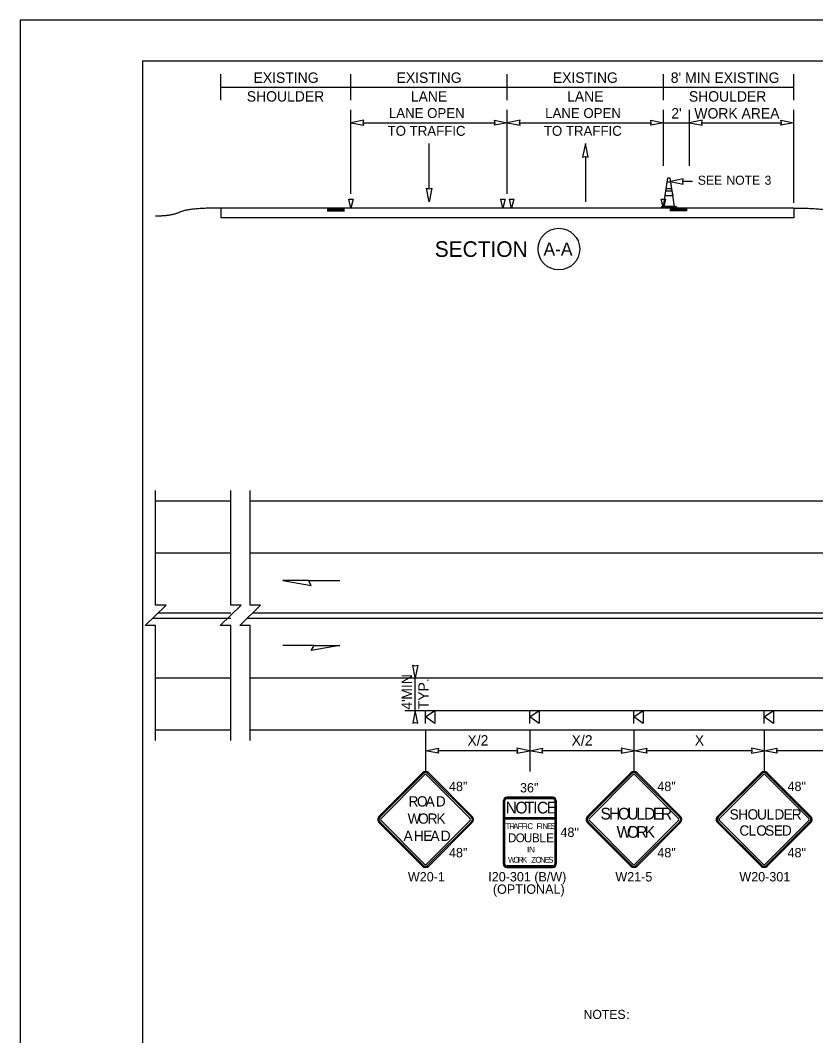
# Model space of a CAD drawing. Extents: x 99999.1 to 100055.7, y 99995 to 100013.2.
# Drawn here: x 99999.06 to 100005.17, y 100002.89 to 100010.69 of the extents above; entities that cross this region are included whole.
import ezdxf

# ---------------------------------------------------------------- set-up
doc = ezdxf.new("R2010")
doc.units = 0
for name, color, linetype in [('RD_ED_ShoulderPavedEdge', 7, 'Continuous'), ('RD_MK_LineDblYellowCenter', 7, 'Continuous'), ('RD_MK_LineEdgeWhite', 7, 'Continuous'), ('SH_GI_GeneralNotesBodyText', 7, 'Continuous'), ('SH_GI_PlotLimits', 7, 'Continuous'), ('SH_GI_SheetBorder', 7, 'Continuous'), ('SH_TI_WZSectionCut', 7, 'Continuous'), ('TR_SN_ConstructionSigns', 7, 'Continuous'), ('TR_WZ_ArrowLeftStrRightTurn', 7, 'Continuous'), ('TR_WZ_PortableSignMountBlk-Org', 7, 'Continuous'), ('TR_WZ_PortableSignMountBlk-Wht', 7, 'Continuous'), ('TR_WZ_TrafficConeElev', 7, 'Continuous'), ('TR_WZ_WorkZoneDetails', 7, 'Continuous'), ('TR_WZ_WorkZoneTextCurrent', 7, 'Continuous')]:
    doc.layers.add(name, color=color, linetype=linetype)

msp = doc.modelspace()

# ---------------------------------------------------------------- linework, layer by layer
at = {"layer": 'RD_ED_ShoulderPavedEdge'}
for p, q in [((100000.1016, 100006.9957), (100000.6783, 100006.9957)), ((100000.8283, 100006.9957), (100015.62, 100006.9957)), ((100000.1016, 100005.2357), (100000.6783, 100005.2357)), ((100000.8283, 100005.2357), (100015.62, 100005.2357))]:
    msp.add_line(p, q, dxfattribs=at)
at = {"layer": 'RD_MK_LineDblYellowCenter'}
for p, q in [((100000.081, 100006.0957), (100000.6783, 100006.0957)), ((100000.1223, 100006.1357), (100000.6783, 100006.1357)), ((100000.8076, 100006.0957), (100015.62, 100006.0957)), ((100000.849, 100006.1357), (100015.62, 100006.1357))]:
    msp.add_line(p, q, dxfattribs=at)
at = {"layer": 'RD_MK_LineEdgeWhite'}
for p, q in [((100000.1016, 100006.5957), (100000.6783, 100006.5957)), ((100000.8283, 100006.5957), (100015.62, 100006.5957)), ((100000.1016, 100005.6357), (100000.6783, 100005.6357)), ((100000.8283, 100005.6357), (100015.62, 100005.6357))]:
    msp.add_line(p, q, dxfattribs=at)
at = {"layer": 'SH_GI_PlotLimits'}
msp.add_lwpolyline([(99999.0625, 99999.6875), (100016.0625, 99999.6875), (100016.0625, 100010.6875), (99999.0625, 100010.6875)], close=True, dxfattribs=at)
at = {"layer": 'SH_GI_SheetBorder'}
for q in [(100000, 100000), (100015.75, 100010.375)]:
    msp.add_line((100000, 100010.375), q, dxfattribs=at)
at = {"layer": 'SH_TI_WZSectionCut'}
for p, q in [((100000.6021, 100010.075), (100000.6021, 100010.275)), ((100001.6021, 100010.075), (100001.6021, 100010.275)), ((100002.8021, 100010.075), (100002.8021, 100010.275)), ((100004.0021, 100010.075), (100004.0021, 100010.275)), ((100005.0021, 100010.075), (100005.0021, 100010.275)), ((100000.6021, 100010.175), (100001.6021, 100010.175)), ((100001.6021, 100010.175), (100002.8021, 100010.175)), ((100002.8021, 100010.175), (100004.0021, 100010.175)), ((100004.0021, 100010.175), (100005.0021, 100010.175)), ((100001.6021, 100009.3547), (100001.6021, 100010.001)), ((100002.8021, 100009.3547), (100002.8021, 100010.001)), ((100004.0021, 100009.57), (100004.0021, 100010.001)), ((100004.2021, 100009.57), (100004.2021, 100010.001)), ((100005.0021, 100009.2849), (100005.0021, 100010.001)), ((100001.6958, 100009.901), (100002.7084, 100009.901)), ((100002.8958, 100009.901), (100003.9084, 100009.901)), ((100004.0021, 100009.901), (100004.2021, 100009.901)), ((100004.2958, 100009.901), (100004.9084, 100009.901)), ((100000.6021, 100009.2449), (100000.6021, 100009.1699)), ((100005.0021, 100009.2449), (100000.6021, 100009.2449)), ((100001.4191, 100009.2397), (100001.5521, 100009.2397)), ((100001.4191, 100009.2341), (100001.5521, 100009.2341)), ((100001.4191, 100009.2284), (100001.5521, 100009.2284)), ((100001.4191, 100009.2232), (100001.5521, 100009.2232)), ((100004.1851, 100009.2393), (100004.0521, 100009.2393)), ((100004.1851, 100009.2337), (100004.0521, 100009.2337)), ((100004.1851, 100009.228), (100004.0521, 100009.228)), ((100004.1851, 100009.2228), (100004.0521, 100009.2228)), ((100005.0021, 100009.2449), (100005.0021, 100009.1699)), ((100005.0021, 100009.1699), (100000.6021, 100009.1699))]:
    msp.add_line(p, q, dxfattribs=at)
for points in [[(100001.6021, 100009.901), (100001.7004, 100009.8817), (100001.6958, 100009.901), (100001.7004, 100009.9203)], [(100002.8021, 100009.901), (100002.7038, 100009.8817), (100002.7084, 100009.901), (100002.7038, 100009.9203)], [(100002.8021, 100009.901), (100002.9004, 100009.8817), (100002.8958, 100009.901), (100002.9004, 100009.9203)], [(100004.0021, 100009.901), (100003.9038, 100009.8817), (100003.9084, 100009.901), (100003.9038, 100009.9203)], [(100004.2021, 100009.901), (100004.3004, 100009.8817), (100004.2958, 100009.901), (100004.3004, 100009.9203)], [(100005.0021, 100009.901), (100004.9038, 100009.8817), (100004.9084, 100009.901), (100004.9038, 100009.9203)], [(100001.5854, 100009.3147), (100001.6188, 100009.3147), (100001.6021, 100009.2449)], [(100002.7521, 100009.3147), (100002.7854, 100009.3147), (100002.7688, 100009.2449)], [(100002.8188, 100009.3147), (100002.8521, 100009.3147), (100002.8355, 100009.2449)], [(100003.9854, 100009.3147), (100004.0188, 100009.3147), (100004.0021, 100009.2449)]]:
    msp.add_lwpolyline(points, close=True, dxfattribs=at)
msp.add_circle((100003.1987, 100008.93), 0.16, dxfattribs=at)
for points in [[(100000.6021, 100009.2449), (100000.3509, 100009.2449), (100000.2255, 100009.1828), (100000.1, 100009.1828)], [(100005.0021, 100009.2449), (100005.2533, 100009.2451), (100005.3788, 100009.183), (100005.5043, 100009.1831)]]:
    msp.add_open_spline(points, degree=2, dxfattribs=at)
at = {"layer": 'TR_SN_ConstructionSigns'}
for p, q in [((100002.1514, 100004.9058), (100001.8173, 100004.5717)), ((100002.1574, 100004.8999), (100001.8233, 100004.5658)), ((100002.5273, 100004.5658), (100002.1932, 100004.8999)), ((100002.5333, 100004.5717), (100002.1991, 100004.9058)), ((100003.7514, 100004.9058), (100003.4173, 100004.5717)), ((100003.7574, 100004.8999), (100003.4233, 100004.5658)), ((100004.1273, 100004.5658), (100003.7932, 100004.8999)), ((100004.1333, 100004.5717), (100003.7991, 100004.9058)), ((100004.7514, 100004.9058), (100004.4173, 100004.5717)), ((100004.7574, 100004.8999), (100004.4233, 100004.5658)), ((100005.1273, 100004.5658), (100004.7932, 100004.8999)), ((100005.1333, 100004.5717), (100004.7991, 100004.9058)), ((100001.8332, 100004.5558), (100002.1673, 100004.8899)), ((100002.1832, 100004.8899), (100002.5173, 100004.5558)), ((100003.4332, 100004.5558), (100003.7673, 100004.8899)), ((100003.7832, 100004.8899), (100004.1173, 100004.5558)), ((100004.4332, 100004.5558), (100004.7673, 100004.8899)), ((100004.7832, 100004.8899), (100005.1173, 100004.5558)), ((100002.7728, 100004.2053), (100002.7728, 100004.6947)), ((100002.7728, 100004.6947), (100002.7728, 100004.2053)), ((100002.7728, 100004.6947), (100002.7728, 100004.2053)), ((100002.777, 100004.6947), (100002.777, 100004.2053)), ((100002.784, 100004.5604), (100002.784, 100004.6947)), ((100002.7981, 100004.72), (100003.1525, 100004.72)), ((100003.1525, 100004.72), (100002.7981, 100004.72)), ((100003.1525, 100004.72), (100002.7981, 100004.72)), ((100003.1525, 100004.7158), (100002.7981, 100004.7158)), ((100002.7981, 100004.7088), (100003.1525, 100004.7088)), ((100003.1665, 100004.6947), (100003.1665, 100004.5604)), ((100003.1736, 100004.2053), (100003.1736, 100004.6947)), ((100003.1778, 100004.6947), (100003.1778, 100004.2053)), ((100003.1778, 100004.2053), (100003.1778, 100004.6947)), ((100003.1778, 100004.2053), (100003.1778, 100004.6947)), ((100001.8173, 100004.524), (100002.1514, 100004.1899)), ((100001.8233, 100004.53), (100002.1574, 100004.1959)), ((100002.1673, 100004.2058), (100001.8332, 100004.5399)), ((100002.5173, 100004.5399), (100002.1832, 100004.2058)), ((100002.1932, 100004.1959), (100002.5273, 100004.53)), ((100002.1991, 100004.1899), (100002.5333, 100004.524)), ((100002.784, 100004.5604), (100002.784, 100004.5604)), ((100003.1665, 100004.5604), (100002.784, 100004.5604)), ((100002.784, 100004.5604), (100002.784, 100004.5534)), ((100002.784, 100004.5534), (100002.784, 100004.5604)), ((100002.784, 100004.5534), (100003.1665, 100004.5534)), ((100002.784, 100004.2053), (100002.784, 100004.5534)), ((100003.1665, 100004.5534), (100003.1665, 100004.5604)), ((100003.1665, 100004.5604), (100003.1665, 100004.5534)), ((100003.1665, 100004.5534), (100003.1665, 100004.2053)), ((100003.4173, 100004.524), (100003.7514, 100004.1899)), ((100003.4233, 100004.53), (100003.7574, 100004.1959)), ((100003.7673, 100004.2058), (100003.4332, 100004.5399)), ((100004.1173, 100004.5399), (100003.7832, 100004.2058)), ((100003.7932, 100004.1959), (100004.1273, 100004.53)), ((100003.7991, 100004.1899), (100004.1333, 100004.524)), ((100004.4173, 100004.524), (100004.7514, 100004.1899)), ((100004.4233, 100004.53), (100004.7574, 100004.1959)), ((100004.7673, 100004.2058), (100004.4332, 100004.5399)), ((100005.1173, 100004.5399), (100004.7832, 100004.2058)), ((100004.7932, 100004.1959), (100005.1273, 100004.53)), ((100004.7991, 100004.1899), (100005.1333, 100004.524)), ((100003.1525, 100004.1913), (100002.7981, 100004.1913)), ((100002.7981, 100004.1842), (100003.1525, 100004.1842)), ((100003.1525, 100004.18), (100002.7981, 100004.18)), ((100002.7981, 100004.18), (100003.1525, 100004.18)), ((100002.7981, 100004.18), (100003.1525, 100004.18))]:
    msp.add_line(p, q, dxfattribs=at)
for centre, radius, start, end in [((100002.1753, 100004.882), 0.0338, 45, 135), ((100002.1753, 100004.882), 0.0253, 45, 135), ((100002.1753, 100004.882), 0.0113, 45, 135), ((100003.7753, 100004.882), 0.0338, 45, 135), ((100003.7753, 100004.882), 0.0253, 45, 135), ((100003.7753, 100004.882), 0.0113, 45, 135), ((100004.7753, 100004.882), 0.0338, 45, 135), ((100004.7753, 100004.882), 0.0253, 45, 135), ((100004.7753, 100004.882), 0.0113, 45, 135), ((100002.7981, 100004.6947), 0.0253, 90, 180), ((100002.7981, 100004.6947), 0.0253, 90, 180), ((100002.7981, 100004.6947), 0.0253, 90, 180), ((100002.7981, 100004.6947), 0.0211, 90, 180.00001), ((100002.7981, 100004.6947), 0.0141, 90, 180.00001), ((100003.1525, 100004.6947), 0.0253, 0, 90), ((100003.1525, 100004.6947), 0.0253, 0, 90), ((100003.1525, 100004.6947), 0.0253, 0, 90), ((100003.1525, 100004.6947), 0.0211, 0, 90), ((100003.1525, 100004.6947), 0.0141, 0, 90), ((100001.8412, 100004.5479), 0.0338, 135, 225.00001), ((100001.8412, 100004.5479), 0.0253, 135, 225.00001), ((100001.8412, 100004.5479), 0.0113, 135, 225.00001), ((100002.5094, 100004.5479), 0.0113, 315.00002, 45), ((100002.5094, 100004.5479), 0.0253, 315.00002, 45), ((100002.5094, 100004.5479), 0.0338, 315.00001, 45.00001), ((100003.4412, 100004.5479), 0.0338, 135, 225.00001), ((100003.4412, 100004.5479), 0.0253, 135, 225.00001), ((100003.4412, 100004.5479), 0.0113, 135, 225.00001), ((100004.1094, 100004.5479), 0.0113, 315.00002, 45), ((100004.1094, 100004.5479), 0.0253, 315.00002, 45), ((100004.1094, 100004.5479), 0.0338, 315.00001, 45.00001), ((100004.4412, 100004.5479), 0.0338, 135, 225.00001), ((100004.4412, 100004.5479), 0.0253, 135, 225.00001), ((100004.4412, 100004.5479), 0.0113, 135, 225.00001), ((100005.1094, 100004.5479), 0.0113, 315.00002, 45), ((100005.1094, 100004.5479), 0.0253, 315.00002, 45), ((100005.1094, 100004.5479), 0.0338, 315.00001, 45.00001), ((100002.1753, 100004.2138), 0.0253, 225.00001, 315.00002), ((100002.1753, 100004.2138), 0.0113, 225.00001, 315.00002), ((100002.7981, 100004.2053), 0.0253, 180, 270.00001), ((100002.7981, 100004.2053), 0.0253, 180, 270.00001), ((100002.7981, 100004.2053), 0.0253, 180, 270.00001), ((100002.7981, 100004.2053), 0.0211, 180.00001, 270), ((100002.7981, 100004.2053), 0.0141, 180.00001, 270), ((100003.1525, 100004.2053), 0.0253, 270.00001, 0.00001), ((100003.1525, 100004.2053), 0.0253, 270.00001, 0.00001), ((100003.1525, 100004.2053), 0.0211, 270, 0.00001), ((100003.1525, 100004.2053), 0.0141, 270, 0.00001), ((100003.1525, 100004.2053), 0.0253, 270.00001, 0.00001), ((100003.7753, 100004.2138), 0.0253, 225.00001, 315.00002), ((100003.7753, 100004.2138), 0.0113, 225.00001, 315.00002), ((100004.7753, 100004.2138), 0.0253, 225.00001, 315.00002), ((100004.7753, 100004.2138), 0.0113, 225.00001, 315.00002), ((100002.1753, 100004.2138), 0.0338, 225.00001, 315.00001), ((100003.7753, 100004.2138), 0.0338, 225.00001, 315.00001), ((100004.7753, 100004.2138), 0.0338, 225.00001, 315.00001)]:
    msp.add_arc(centre, radius, start, end, dxfattribs=at)
at = {"layer": 'TR_WZ_ArrowLeftStrRightTurn'}
for p, q in [((100002.2021, 100009.3922), (100002.2021, 100009.742)), ((100003.4021, 100009.6418), (100003.4021, 100009.292))]:
    msp.add_line(p, q, dxfattribs=at)
for points in [[(100003.4021, 100009.742), (100003.3815, 100009.6369), (100003.4021, 100009.6418), (100003.4227, 100009.6369)], [(100002.2021, 100009.292), (100002.1815, 100009.397), (100002.2021, 100009.3922), (100002.2227, 100009.397)]]:
    msp.add_lwpolyline(points, close=True, dxfattribs=at)
at = {"layer": 'TR_WZ_PortableSignMountBlk-Org'}
for p, q in [((100002.1753, 100005.2858), (100002.1753, 100005.3858)), ((100003.7753, 100005.2858), (100003.7753, 100005.3858)), ((100004.7753, 100005.2858), (100004.7753, 100005.3858))]:
    msp.add_line(p, q, dxfattribs=at)
for points in [[(100002.1753, 100005.3357), (100002.2471, 100005.3858), (100002.2471, 100005.2858)], [(100003.7753, 100005.3357), (100003.8471, 100005.3858), (100003.8471, 100005.2858)], [(100004.7753, 100005.3357), (100004.8471, 100005.3858), (100004.8471, 100005.2858)]]:
    msp.add_lwpolyline(points, close=True, dxfattribs=at)
at = {"layer": 'TR_WZ_PortableSignMountBlk-Wht'}
msp.add_line((100002.9753, 100005.2857), (100002.9753, 100005.3857), dxfattribs=at)
msp.add_lwpolyline([(100002.9753, 100005.3356), (100003.0471, 100005.3857), (100003.0471, 100005.2857)], close=True, dxfattribs=at)
at = {"layer": 'TR_WZ_TrafficConeElev'}
for p, q in [((100004.0229, 100009.3929), (100004.0312, 100009.4471)), ((100004.0312, 100009.4471), (100004.0564, 100009.4471)), ((100004.0564, 100009.4471), (100004.0647, 100009.3929)), ((100004.0146, 100009.3388), (100004.0203, 100009.3763)), ((100004.0203, 100009.3763), (100004.0672, 100009.3763)), ((100004.0647, 100009.3929), (100004.0229, 100009.3929)), ((100004.0672, 100009.3763), (100004.073, 100009.3388)), ((100004.073, 100009.3388), (100004.0146, 100009.3388)), ((100003.986, 100009.2533), (100003.9901, 100009.2575)), ((100003.986, 100009.245), (100003.986, 100009.2533)), ((100004.1016, 100009.245), (100003.986, 100009.245)), ((100004.0854, 100009.2575), (100004.0974, 100009.2575)), ((100004.0974, 100009.2575), (100004.1016, 100009.2533)), ((100004.1016, 100009.2533), (100004.1016, 100009.245))]:
    msp.add_line(p, q, dxfattribs=at)
msp.add_lwpolyline([(100004.0854, 100009.2575), (100004.0021, 100009.2575), (100004.036, 100009.4783), (100004.0516, 100009.4783)], close=True, dxfattribs=at)
msp.add_lwpolyline([(100004.0854, 100009.2575), (100004.0021, 100009.2575), (100004.036, 100009.4783), (100004.0516, 100009.4783)], close=True, dxfattribs=at)
msp.add_lwpolyline([(100003.9901, 100009.2575), (100004.0021, 100009.2575), (100004.0854, 100009.2575)], dxfattribs=at)
at = {"layer": 'TR_WZ_WorkZoneDetails'}
for p, q in [((100004.226, 100009.4491), (100004.1498, 100009.4491)), ((100001.2748, 100006.385), (100001.516, 100006.385)), ((100001.3194, 100005.885), (100001.0783, 100005.885)), ((100002.0153, 100005.6357), (100002.1753, 100005.6357)), ((100002.0953, 100005.3858), (100002.0953, 100005.6357)), ((100002.0153, 100005.3858), (100002.1753, 100005.3858)), ((100002.1753, 100005.3858), (100005.7753, 100005.3858)), ((100002.1753, 100005.2357), (100002.1753, 100004.9157)), ((100002.9753, 100005.236), (100002.9753, 100004.9157)), ((100003.7753, 100005.236), (100003.7753, 100004.9157)), ((100004.7753, 100005.236), (100004.7753, 100004.9157)), ((100002.8815, 100005.0757), (100002.269, 100005.0757)), ((100003.6815, 100005.0757), (100003.069, 100005.0757)), ((100004.6815, 100005.0757), (100003.869, 100005.0757)), ((100005.6815, 100005.0757), (100004.869, 100005.0757))]:
    msp.add_line(p, q, dxfattribs=at)
for points in [[(100004.0561, 100009.4492), (100004.1544, 100009.4299), (100004.1498, 100009.4492), (100004.1543, 100009.4685)], [(100001.0783, 100006.385), (100001.2971, 100006.3464), (100001.2748, 100006.385)], [(100001.516, 100005.885), (100001.2971, 100005.8464), (100001.3194, 100005.885)], [(100002.0953, 100005.6357), (100002.076, 100005.734), (100002.0953, 100005.7295), (100002.1146, 100005.734)], [(100002.0953, 100005.3858), (100002.076, 100005.2875), (100002.0953, 100005.2921), (100002.1146, 100005.2875)], [(100002.1753, 100005.0757), (100002.2736, 100005.095), (100002.269, 100005.0757), (100002.2736, 100005.0565)], [(100002.9753, 100005.0757), (100002.877, 100005.095), (100002.8815, 100005.0757), (100002.877, 100005.0565)], [(100002.9753, 100005.0757), (100003.0736, 100005.095), (100003.069, 100005.0757), (100003.0736, 100005.0565)], [(100003.7753, 100005.0757), (100003.677, 100005.095), (100003.6815, 100005.0757), (100003.677, 100005.0565)], [(100003.7753, 100005.0757), (100003.8736, 100005.095), (100003.869, 100005.0757), (100003.8736, 100005.0565)], [(100004.7753, 100005.0757), (100004.677, 100005.095), (100004.6815, 100005.0757), (100004.677, 100005.0565)], [(100004.7753, 100005.0757), (100004.8736, 100005.095), (100004.869, 100005.0757), (100004.8736, 100005.0565)]]:
    msp.add_lwpolyline(points, close=True, dxfattribs=at)
for points in [[(100000.1016, 100005.1557), (100000.1016, 100006.0383), (100000.0216, 100006.0383), (100000.1817, 100006.1932), (100000.1016, 100006.1932), (100000.1016, 100007.0757)], [(100000.6783, 100005.1557), (100000.6783, 100006.0383), (100000.5983, 100006.0383), (100000.7583, 100006.1932), (100000.6783, 100006.1932), (100000.6783, 100007.0757)], [(100000.8283, 100005.1557), (100000.8283, 100006.0383), (100000.7483, 100006.0383), (100000.9083, 100006.1932), (100000.8283, 100006.1932), (100000.8283, 100007.0757)]]:
    msp.add_lwpolyline(points, dxfattribs=at)

# ---------------------------------------------------------------- texts
at = {"layer": 'SH_GI_GeneralNotesBodyText'}
for s, p in [('NOTES', (100003.3886, 100003.0156)), (':', (100003.7161, 100003.0156))]:
    msp.add_text(s, height=0.07, rotation=360, dxfattribs=at).set_placement(p)
at = {"layer": 'SH_TI_WZSectionCut'}
for s, height, p in [('EXISTING', 0.08, (100000.8538, 100010.207)), ('EXISTING', 0.08, (100001.9523, 100010.207)), ('EXISTING', 0.08, (100003.1523, 100010.207)), ("8' MIN EXISTING", 0.08, (100004.0582, 100010.207)), ('SHOULDER', 0.08, (100000.8019, 100010.063)), ('LANE', 0.08, (100002.0617, 100010.063)), ('LANE', 0.08, (100003.2617, 100010.063)), ('SHOULDER', 0.08, (100004.1973, 100010.063)), ('SECTION', 0.12, (100002.2456, 100008.87)), ('A-A', 0.1, (100003.0808, 100008.88))]:
    msp.add_text(s, height=height, rotation=360, dxfattribs=at).set_placement(p)
for s, height, p in [('LANE OPEN', 0.076, (100001.8934, 100009.937)), ('LANE OPEN', 0.076, (100003.0934, 100009.937)), ("2'", 0.08, (100004.0621, 100009.933)), ('WORK AREA', 0.08, (100004.2392, 100009.933)), ('TO TRAFFIC', 0.076, (100001.8834, 100009.8002)), ('TO TRAFFIC', 0.076, (100003.0834, 100009.8002))]:
    msp.add_text(s, height=height, dxfattribs=at).set_placement(p)
at = {"layer": 'TR_SN_ConstructionSigns'}
for s, p in [('48"', (100002.3551, 100004.7664)), ('36"', (100002.9005, 100004.756)), ('48"', (100003.9551, 100004.7664)), ('48"', (100004.9551, 100004.7664)), ('48"', (100003.211, 100004.414)), ('48"', (100002.3551, 100004.2573)), ('48"', (100003.9551, 100004.2573)), ('48"', (100004.9551, 100004.2573)), ('W20-1', (100002.0395, 100004.072)), ('I20-301 (B/W)', (100002.6567, 100004.072)), ('W21-5', (100003.6327, 100004.072)), ('W20-301', (100004.5851, 100004.072)), ('(OPTIONAL)', (100002.6921, 100003.9769))]:
    msp.add_text(s, height=0.072, rotation=360, dxfattribs=at).set_placement(p)
for s, height, p in [('R', 0.0788, (100002.0434, 100004.6477)), ('O', 0.0788, (100002.1087, 100004.6477)), ('A', 0.0788, (100002.1749, 100004.6477)), ('D', 0.0788, (100002.2536, 100004.6477)), ('N', 0.09, (100002.7895, 100004.5942)), ('O', 0.09, (100002.8646, 100004.5942)), ('T', 0.09, (100002.9367, 100004.5942)), ('I', 0.09, (100003.0019, 100004.5942)), ('C', 0.09, (100003.0302, 100004.5942)), ('E', 0.09, (100003.1052, 100004.5942)), ('W', 0.0788, (100002.0375, 100004.5155)), ('O', 0.0788, (100002.1178, 100004.5155)), ('R', 0.0788, (100002.191, 100004.5155)), ('K', 0.0788, (100002.258, 100004.5155)), ('S', 0.09, (100003.5183, 100004.5479)), ('H', 0.09, (100003.584, 100004.5479)), ('O', 0.09, (100003.6524, 100004.5479)), ('U', 0.09, (100003.7235, 100004.5479)), ('L', 0.09, (100003.7937, 100004.5479)), ('D', 0.09, (100003.8522, 100004.5479)), ('E', 0.09, (100003.9206, 100004.5479)), ('R', 0.09, (100003.9818, 100004.5479)), ('S', 0.0787, (100004.5099, 100004.5479)), ('H', 0.0787, (100004.5768, 100004.5479)), ('O', 0.0787, (100004.6477, 100004.5479)), ('U', 0.0787, (100004.7209, 100004.5479)), ('L', 0.0787, (100004.7934, 100004.5479)), ('D', 0.0787, (100004.854, 100004.5479)), ('E', 0.0787, (100004.9249, 100004.5479)), ('R', 0.0787, (100004.9871, 100004.5479)), ('T', 0.045, (100002.7894, 100004.4746)), ('R', 0.045, (100002.8187, 100004.4746)), ('A', 0.045, (100002.8479, 100004.4746)), ('F', 0.045, (100002.883, 100004.4746)), ('F', 0.045, (100002.9123, 100004.4746)), ('I', 0.045, (100002.9415, 100004.4746)), ('C', 0.045, (100002.9568, 100004.4746)), ('F', 0.045, (100003.027, 100004.4746)), ('I', 0.045, (100003.0563, 100004.4746)), ('N', 0.045, (100003.0725, 100004.4746)), ('E', 0.045, (100003.1076, 100004.4746)), ('S', 0.045, (100003.1359, 100004.4746)), ('C', 0.0787, (100004.5851, 100004.4241)), ('L', 0.0787, (100004.656, 100004.4241)), ('O', 0.0787, (100004.715, 100004.4241)), ('S', 0.0787, (100004.7828, 100004.4241)), ('E', 0.0787, (100004.8497, 100004.4241)), ('D', 0.0787, (100004.9119, 100004.4241)), ('A', 0.0788, (100002.006, 100004.3833)), ('H', 0.0788, (100002.0847, 100004.3833)), ('E', 0.0788, (100002.1572, 100004.3833)), ('A', 0.0788, (100002.2123, 100004.3833)), ('D', 0.0788, (100002.291, 100004.3833)), ('D', 0.0675, (100002.8075, 100004.3734)), ('O', 0.0675, (100002.8669, 100004.3734)), ('U', 0.0675, (100002.9297, 100004.3734)), ('B', 0.0675, (100002.9918, 100004.3734)), ('L', 0.0675, (100003.0492, 100004.3734)), ('E', 0.0675, (100003.1012, 100004.3734)), ('W', 0.09, (100003.6421, 100004.4072)), ('O', 0.09, (100003.7213, 100004.4072)), ('R', 0.09, (100003.7924, 100004.4072)), ('K', 0.09, (100003.8581, 100004.4072)), ('I', 0.045, (100002.9546, 100004.2946)), ('N', 0.045, (100002.9708, 100004.2946)), ('W', 0.045, (100002.8081, 100004.2159)), ('O', 0.045, (100002.8477, 100004.2159)), ('R', 0.045, (100002.8833, 100004.2159)), ('K', 0.045, (100002.9161, 100004.2159)), ('Z', 0.045, (100002.9863, 100004.2159)), ('O', 0.045, (100003.0183, 100004.2159)), ('N', 0.045, (100003.0538, 100004.2159)), ('E', 0.045, (100003.0889, 100004.2159)), ('S', 0.045, (100003.1173, 100004.2159))]:
    msp.add_text(s, height=height, dxfattribs=at).set_placement(p)
at = {"layer": 'TR_WZ_WorkZoneTextCurrent'}
for s, p in [('SEE', (100004.266, 100009.4241)), ('NOTE', (100004.4853, 100009.4241)), ('3', (100004.7785, 100009.4241))]:
    msp.add_text(s, height=0.07, dxfattribs=at).set_placement(p)
for s, rotation, p in [('MIN', 90, (100002.0713, 100005.4682)), ('TYP.', 90, (100002.1993, 100005.3954)), ("4'", 90, (100002.0713, 100005.3917)), ('X/2', 360, (100002.4968, 100005.1157)), ('X/2', 360, (100003.2968, 100005.1157)), ('X', 360, (100004.2428, 100005.1157))]:
    msp.add_text(s, height=0.08, rotation=rotation, dxfattribs=at).set_placement(p)

doc.saveas('drawing.dxf')
